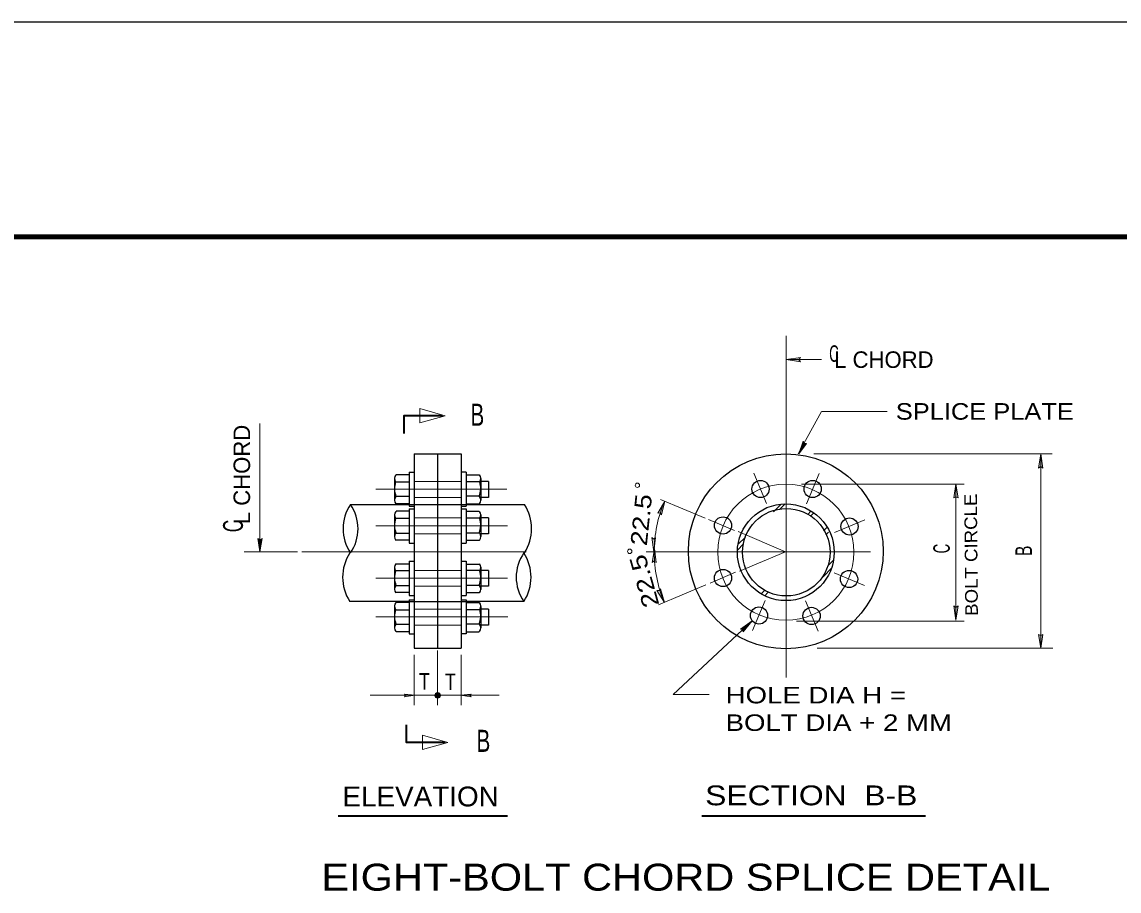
# Model space of a CAD drawing. Extents: x 312601.858 to 312602.699, y 144420.109 to 144420.704.
# Drawn here: x 312602.0898 to 312602.2889, y 144420.5457 to 144420.7035 of the extents above; entities that cross this region are included whole.
import ezdxf
from ezdxf.enums import TextEntityAlignment as Align

# ---------------------------------------------------------------- set-up
doc = ezdxf.new("R2010")
doc.units = 0
doc.header["$LTSCALE"] = 0.0012
for name, pattern in [('DOT_DASHED', [7.7, 5, -1.2, 0.3, -1.2]), ('LONG_DASHED', [7.5, 6, -1.5]), ('MEDIUM_DASHED', [4.5, 3, -1.5])]:
    doc.linetypes.add(name, pattern=pattern)
for name, color, linetype, lineweight in [('1', 7, 'Continuous', 25), ('2', 7, 'Continuous', 13), ('39', 7, 'Continuous', 13), ('9', 7, 'Continuous', 13)]:
    doc.layers.add(name, color=color, linetype=linetype, lineweight=lineweight)

msp = doc.modelspace()

# ---------------------------------------------------------------- hatches: boundary and pattern name
at = {"layer": '1'}
msp.add_hatch(color=256, dxfattribs=at).paths.add_polyline_path([(312602.16575, 144420.58125, 1), (312602.16473, 144420.58125, 1)])
at = {"layer": '39'}
for points in [[(312602.2308, 144420.6422), (312602.2311, 144420.6418), (312602.2285, 144420.6422), (312602.2311, 144420.6426)], [(312602.2318, 144420.627), (312602.2322, 144420.627), (312602.2308, 144420.6251), (312602.2316, 144420.6274)], [(312602.2747, 144420.6228), (312602.2743, 144420.6225), (312602.2747, 144420.6251), (312602.2751, 144420.6225)], [(312602.2747, 144420.6228), (312602.2743, 144420.6225), (312602.2747, 144420.6251), (312602.2751, 144420.6225)], [(312602.2593, 144420.6173), (312602.2589, 144420.6171), (312602.2593, 144420.6196), (312602.2597, 144420.6171)], [(312602.2593, 144420.6173), (312602.2589, 144420.6171), (312602.2593, 144420.6196), (312602.2597, 144420.6171)], [(312602.2056, 144420.6144), (312602.2052, 144420.6143), (312602.2065, 144420.6165), (312602.2059, 144420.614)], [(312602.2045, 144420.6096), (312602.2048, 144420.6099), (312602.2045, 144420.6073), (312602.2041, 144420.6099)], [(312602.133, 144420.6095), (312602.1334, 144420.6097), (312602.133, 144420.6073), (312602.1326, 144420.6097)], [(312602.133, 144420.6095), (312602.1334, 144420.6097), (312602.133, 144420.6073), (312602.1326, 144420.6097)], [(312602.2045, 144420.6056), (312602.2042, 144420.6054), (312602.2046, 144420.6079), (312602.2049, 144420.6054)], [(312602.2055, 144420.6003), (312602.2057, 144420.6006), (312602.2064, 144420.5981), (312602.205, 144420.6003)], [(312602.2593, 144420.5972), (312602.2597, 144420.5975), (312602.2593, 144420.5949), (312602.2589, 144420.5975)], [(312602.2206, 144420.5932), (312602.2202, 144420.5933), (312602.2223, 144420.5948), (312602.2207, 144420.5928)], [(312602.2747, 144420.5921), (312602.2751, 144420.5923), (312602.2747, 144420.5898), (312602.2743, 144420.5923)]]:
    msp.add_hatch(color=256, dxfattribs=at).paths.add_polyline_path(points)

# ---------------------------------------------------------------- linework, layer by layer
at = {"layer": '1', "lineweight": 13}
for p, q in [((312602.2285, 144420.6372), (312602.2285, 144420.6465)), ((312602.2285, 144420.6422), (312602.2349, 144420.6422)), ((312602.2349, 144420.6328), (312602.2307, 144420.6251)), ((312602.235, 144420.6328), (312602.2468, 144420.6328)), ((312602.133, 144420.6073), (312602.133, 144420.6306)), ((312602.2335, 144420.6251), (312602.2768, 144420.6251)), ((312602.2747, 144420.5898), (312602.2747, 144420.6251)), ((312602.1745, 144420.6199), (312602.1745, 144420.6201)), ((312602.2313, 144420.6196), (312602.2608, 144420.6196)), ((312602.2593, 144420.5949), (312602.2593, 144420.6196)), ((312602.2138, 144420.6134), (312602.2057, 144420.6168)), ((312602.1745, 144420.6133), (312602.1745, 144420.6135)), ((312602.2284, 144420.6073), (312602.2198, 144420.611)), ((312602.1398, 144420.6073), (312602.1301, 144420.6073)), ((312602.2031, 144420.6073), (312602.2087, 144420.6073)), ((312602.2284, 144420.6073), (312602.22, 144420.6038)), ((312602.1745, 144420.6038), (312602.1745, 144420.6039)), ((312602.2139, 144420.6013), (312602.2053, 144420.5977)), ((312602.1574, 144420.5974), (312602.1574, 144420.5935)), ((312602.1745, 144420.5967), (312602.1745, 144420.5969)), ((312602.208, 144420.5814), (312602.2223, 144420.5948)), ((312602.2304, 144420.5947), (312602.2608, 144420.5947)), ((312602.161, 144420.5886), (312602.161, 144420.5795)), ((312602.1652, 144420.5894), (312602.1652, 144420.5795)), ((312602.1695, 144420.5886), (312602.1695, 144420.5795)), ((312602.2341, 144420.5898), (312602.2769, 144420.5898)), ((312602.153, 144420.5813), (312602.1764, 144420.5813)), ((312602.208, 144420.5814), (312602.2145, 144420.5814))]:
    msp.add_line(p, q, dxfattribs=at)
at = {"layer": '1', "linetype": 'DOT_DASHED', "lineweight": 13}
for p, q in [((312602.2285, 144420.5845), (312602.2285, 144420.6465)), ((312602.2249, 144420.6161), (312602.2226, 144420.6216)), ((312602.2322, 144420.616), (312602.2345, 144420.6215)), ((312602.1778, 144420.6187), (312602.154, 144420.6187)), ((312602.1779, 144420.612), (312602.154, 144420.612)), ((312602.2191, 144420.6112), (312602.2144, 144420.6132)), ((312602.2373, 144420.6108), (312602.2428, 144420.6131)), ((312602.1813, 144420.6073), (312602.1406, 144420.6073)), ((312602.204, 144420.6073), (312602.2438, 144420.6073)), ((312602.1779, 144420.6025), (312602.154, 144420.6025)), ((312602.2193, 144420.6036), (312602.2147, 144420.6016)), ((312602.2372, 144420.6035), (312602.2427, 144420.6012)), ((312602.2247, 144420.5985), (312602.2224, 144420.593)), ((312602.232, 144420.5984), (312602.2343, 144420.5929)), ((312602.178, 144420.5955), (312602.154, 144420.5955))]:
    msp.add_line(p, q, dxfattribs=at)
at = {"layer": '1'}
for p, q in [((312602.161, 144420.6251), (312602.161, 144420.5898)), ((312602.161, 144420.6251), (312602.1695, 144420.6251)), ((312602.1652, 144420.6251), (312602.1652, 144420.5898)), ((312602.1695, 144420.6251), (312602.1695, 144420.5898)), ((312602.1601, 144420.6218), (312602.161, 144420.6218)), ((312602.1601, 144420.6218), (312602.1601, 144420.6156)), ((312602.1704, 144420.6218), (312602.1695, 144420.6218)), ((312602.1704, 144420.6218), (312602.1704, 144420.6156)), ((312602.1574, 144420.6206), (312602.1574, 144420.6167)), ((312602.1576, 144420.62), (312602.1601, 144420.62)), ((312602.1601, 144420.6213), (312602.1577, 144420.6213)), ((312602.1704, 144420.6213), (312602.1728, 144420.6213)), ((312602.1729, 144420.62), (312602.1704, 144420.62)), ((312602.1731, 144420.6206), (312602.1731, 144420.6167)), ((312602.1745, 144420.6201), (312602.1731, 144420.6201)), ((312602.1745, 144420.6201), (312602.1745, 144420.6172)), ((312602.1494, 144420.6159), (312602.1601, 144420.6159)), ((312602.1577, 144420.6174), (312602.1601, 144420.6174)), ((312602.1601, 144420.616), (312602.1577, 144420.616)), ((312602.1728, 144420.6174), (312602.1704, 144420.6174)), ((312602.1704, 144420.616), (312602.1728, 144420.616)), ((312602.1704, 144420.6159), (312602.181, 144420.6159)), ((312602.1745, 144420.6172), (312602.1731, 144420.6172)), ((312602.1574, 144420.614), (312602.1574, 144420.6101)), ((312602.1601, 144420.6147), (312602.1577, 144420.6147)), ((312602.1601, 144420.6156), (312602.161, 144420.6156)), ((312602.1601, 144420.6151), (312602.1601, 144420.6089)), ((312602.1601, 144420.6151), (312602.161, 144420.6151)), ((312602.1695, 144420.6156), (312602.1704, 144420.6156)), ((312602.1695, 144420.6151), (312602.1704, 144420.6151)), ((312602.1704, 144420.6151), (312602.1704, 144420.6089)), ((312602.1704, 144420.6147), (312602.1728, 144420.6147)), ((312602.1731, 144420.614), (312602.1731, 144420.6101)), ((312602.1576, 144420.6134), (312602.1601, 144420.6134)), ((312602.1729, 144420.6134), (312602.1704, 144420.6134)), ((312602.1745, 144420.6135), (312602.1731, 144420.6135)), ((312602.1745, 144420.6135), (312602.1745, 144420.6106)), ((312602.1577, 144420.6107), (312602.1601, 144420.6107)), ((312602.1728, 144420.6107), (312602.1704, 144420.6107)), ((312602.1745, 144420.6106), (312602.1731, 144420.6106)), ((312602.1601, 144420.6094), (312602.1577, 144420.6094)), ((312602.1601, 144420.6089), (312602.161, 144420.6089)), ((312602.1695, 144420.6089), (312602.1704, 144420.6089)), ((312602.1704, 144420.6094), (312602.1728, 144420.6094)), ((312602.1574, 144420.6045), (312602.1574, 144420.6005)), ((312602.16, 144420.6051), (312602.1576, 144420.6051)), ((312602.1576, 144420.6039), (312602.16, 144420.6039)), ((312602.1576, 144420.6039), (312602.1601, 144420.6039)), ((312602.1601, 144420.6051), (312602.1577, 144420.6051)), ((312602.1601, 144420.6056), (312602.1601, 144420.5994)), ((312602.1601, 144420.6056), (312602.161, 144420.6056)), ((312602.1695, 144420.6056), (312602.1704, 144420.6056)), ((312602.1704, 144420.6056), (312602.1704, 144420.5994)), ((312602.1704, 144420.6051), (312602.1728, 144420.6051)), ((312602.1729, 144420.6039), (312602.1704, 144420.6039)), ((312602.1731, 144420.6045), (312602.1731, 144420.6005)), ((312602.1745, 144420.6039), (312602.1731, 144420.6039)), ((312602.1745, 144420.6039), (312602.1745, 144420.6011)), ((312602.1577, 144420.6012), (312602.16, 144420.6012)), ((312602.1577, 144420.6012), (312602.1601, 144420.6012)), ((312602.16, 144420.5999), (312602.1577, 144420.5999)), ((312602.1601, 144420.5999), (312602.1577, 144420.5999)), ((312602.1728, 144420.6012), (312602.1704, 144420.6012)), ((312602.1704, 144420.5999), (312602.1728, 144420.5999)), ((312602.1745, 144420.6011), (312602.1731, 144420.6011)), ((312602.1601, 144420.5983), (312602.1493, 144420.5983)), ((312602.1601, 144420.5981), (312602.1577, 144420.5981)), ((312602.1601, 144420.5981), (312602.1577, 144420.5981)), ((312602.1601, 144420.5994), (312602.161, 144420.5994)), ((312602.1601, 144420.5986), (312602.1601, 144420.5924)), ((312602.1601, 144420.5986), (312602.161, 144420.5986)), ((312602.1695, 144420.5994), (312602.1704, 144420.5994)), ((312602.1695, 144420.5986), (312602.1704, 144420.5986)), ((312602.1704, 144420.5986), (312602.1704, 144420.5924)), ((312602.1809, 144420.5983), (312602.1704, 144420.5983)), ((312602.1704, 144420.5981), (312602.1728, 144420.5981)), ((312602.1574, 144420.5974), (312602.1574, 144420.5935)), ((312602.1576, 144420.5968), (312602.1601, 144420.5968)), ((312602.1729, 144420.5968), (312602.1704, 144420.5968)), ((312602.1731, 144420.5974), (312602.1731, 144420.5935)), ((312602.1745, 144420.5969), (312602.1731, 144420.5969)), ((312602.1745, 144420.5969), (312602.1745, 144420.594)), ((312602.1577, 144420.5942), (312602.1601, 144420.5942)), ((312602.1577, 144420.5942), (312602.1601, 144420.5942)), ((312602.1728, 144420.5942), (312602.1704, 144420.5942)), ((312602.1745, 144420.594), (312602.1731, 144420.594)), ((312602.1601, 144420.5928), (312602.1577, 144420.5928)), ((312602.1601, 144420.5928), (312602.1577, 144420.5928)), ((312602.1601, 144420.5924), (312602.161, 144420.5924)), ((312602.1704, 144420.5924), (312602.1695, 144420.5924)), ((312602.1704, 144420.5928), (312602.1728, 144420.5928)), ((312602.161, 144420.5898), (312602.1695, 144420.5898))]:
    msp.add_line(p, q, dxfattribs=at)
at = {"layer": '1', "linetype": 'MEDIUM_DASHED', "lineweight": 13}
for p, q in [((312602.1695, 144420.6201), (312602.161, 144420.6201)), ((312602.1695, 144420.6172), (312602.1611, 144420.6172)), ((312602.1695, 144420.6135), (312602.161, 144420.6135)), ((312602.1695, 144420.6106), (312602.1611, 144420.6106)), ((312602.1695, 144420.6039), (312602.161, 144420.6039)), ((312602.1695, 144420.6011), (312602.1611, 144420.6011)), ((312602.1695, 144420.5969), (312602.161, 144420.5969)), ((312602.1695, 144420.594), (312602.1611, 144420.594))]:
    msp.add_line(p, q, dxfattribs=at)
at = {"layer": '1', "linetype": 'LONG_DASHED'}
for p, q in [((312602.1548, 144420.6159), (312602.1588, 144420.6159)), ((312602.1602, 144420.6159), (312602.1703, 144420.6159)), ((312602.1601, 144420.5983), (312602.1703, 144420.5983))]:
    msp.add_line(p, q, dxfattribs=at)
at = {"layer": '1', "lineweight": 35}
for points in [[(312602.1661, 144420.632), (312602.1591, 144420.632), (312602.1591, 144420.6288)], [(312602.1666, 144420.5727), (312602.1596, 144420.5727), (312602.1596, 144420.5759)]]:
    msp.add_lwpolyline(points, dxfattribs=at)
at = {"layer": '1'}
for centre, radius in [((312602.228435, 144420.607405), 0.017693), ((312602.223845, 144420.61871), 0.00156), ((312602.233303, 144420.618715), 0.00156), ((312602.228435, 144420.607235), 0.008788), ((312602.22852, 144420.607235), 0.007942), ((312602.21704, 144420.612103), 0.00156), ((312602.239995, 144420.61191), 0.00156), ((312602.217045, 144420.60256), 0.00156), ((312602.239915, 144420.602367), 0.00156), ((312602.223567, 144420.595755), 0.00156), ((312602.23311, 144420.595675), 0.00156)]:
    msp.add_circle(centre, radius, dxfattribs=at)
at = {"layer": '1', "linetype": 'DOT_DASHED', "lineweight": 13}
msp.add_circle((312602.228435, 144420.607235), 0.012354, dxfattribs=at)
at = {"layer": '1', "lineweight": 13}
msp.add_circle((312602.16524, 144420.58125), 0.00051, dxfattribs=at)
at = {"layer": '1'}
for centre, radius, start, end in [((312602.161585, 144420.61882), 0.004169, 163.41266, 200.28256), ((312602.158525, 144420.620605), 0.001105, 142.02013, 212.47565), ((312602.168895, 144420.61882), 0.004169, 339.71744, 16.58734), ((312602.171955, 144420.620605), 0.001105, 327.52435, 37.97987), ((312602.158525, 144420.616695), 0.001105, 142.02013, 217.97987), ((312602.171955, 144420.616695), 0.001105, 322.02013, 37.97987), ((312602.158525, 144420.613975), 0.001105, 142.02013, 212.47565), ((312602.171955, 144420.613975), 0.001105, 327.52435, 37.97987), ((312602.161585, 144420.61219), 0.004169, 163.41266, 200.28256), ((312602.168895, 144420.61219), 0.004169, 339.71744, 16.58734), ((312602.158525, 144420.610065), 0.001105, 142.02013, 217.97987), ((312602.171955, 144420.610065), 0.001105, 322.02013, 37.97987), ((312602.161585, 144420.60267), 0.004169, 163.41266, 200.28256), ((312602.158525, 144420.604455), 0.001105, 142.02013, 212.47565), ((312602.168895, 144420.60267), 0.004169, 339.71744, 16.58734), ((312602.171955, 144420.604455), 0.001105, 327.52435, 37.97987), ((312602.158525, 144420.600545), 0.001105, 142.02013, 217.97987), ((312602.171955, 144420.600545), 0.001105, 322.02013, 37.97987), ((312602.158525, 144420.597425), 0.001105, 142.02013, 212.47565), ((312602.171955, 144420.597425), 0.001105, 327.52435, 37.97987), ((312602.161585, 144420.59564), 0.004169, 163.41266, 200.28256), ((312602.168895, 144420.59564), 0.004169, 339.71744, 16.58734), ((312602.158525, 144420.593515), 0.001105, 142.02013, 217.97987), ((312602.171955, 144420.593515), 0.001105, 322.02013, 37.97987)]:
    msp.add_arc(centre, radius, start, end, dxfattribs=at)
at = {"layer": '1', "lineweight": 13}
for centre, radius, start, end in [((312602.228435, 144420.607235), 0.023885, 157.17624, 179.78525), ((312602.228435, 144420.607235), 0.023885, 179.79611, 179.80295), ((312602.228435, 144420.607235), 0.023885, 179.7961, 202.45151), ((312602.158525, 144420.597425), 0.001105, 142.02013, 212.47565), ((312602.161585, 144420.59564), 0.004169, 163.41266, 200.28256), ((312602.158525, 144420.593515), 0.001105, 142.02013, 217.97987)]:
    msp.add_arc(centre, radius, start, end, dxfattribs=at)
at = {"layer": '2'}
for p, q in [((312602.2262, 144420.6146), (312602.2275, 144420.6159)), ((312602.2273, 144420.615), (312602.2283, 144420.616)), ((312602.2324, 144420.6141), (312602.233, 144420.6147)), ((312602.2329, 144420.6138), (312602.2335, 144420.6144)), ((312602.2198, 144420.6087), (312602.2211, 144420.61)), ((312602.2353, 144420.6111), (312602.2359, 144420.6117)), ((312602.2357, 144420.6104), (312602.2362, 144420.6109)), ((312602.2197, 144420.6077), (312602.2207, 144420.6087)), ((312602.2361, 144420.6048), (312602.2371, 144420.6058)), ((312602.2352, 144420.6028), (312602.2368, 144420.6044)), ((312602.2239, 144420.5996), (312602.2245, 144420.6002)), ((312602.2246, 144420.5993), (312602.2252, 144420.5999))]:
    msp.add_line(p, q, dxfattribs=at)
at = {"layer": '2', "lineweight": 35}
for p, q in [((312602.1472, 144420.5594), (312602.1779, 144420.5594)), ((312602.2132, 144420.5594), (312602.2538, 144420.5594))]:
    msp.add_line(p, q, dxfattribs=at)
at = {"layer": '2'}
for points in [[(312602.1592, 144420.5815), (312602.1611, 144420.5813), (312602.1592, 144420.581), (312602.1594, 144420.5813)], [(312602.1713, 144420.5815), (312602.1694, 144420.5813), (312602.1713, 144420.581), (312602.1711, 144420.5813)]]:
    msp.add_lwpolyline(points, close=True, dxfattribs=at)
for centre in [(312602.2015, 144420.6194), (312602.2001, 144420.6074)]:
    msp.add_circle(centre, 0.0004, dxfattribs=at)
at = {"layer": '2', "lineweight": 25}
for centre, radius, start, end in [((312602.156192, 144420.6115), 0.008093, 147.06517, 212.93482), ((312602.143186, 144420.6115), 0.007614, 324.69975, 35.30025), ((312602.174208, 144420.6115), 0.008093, 327.06517, 32.93482), ((312602.156092, 144420.6027), 0.008093, 147.06517, 212.93482), ((312602.187114, 144420.6027), 0.007614, 144.69975, 215.30025), ((312602.174108, 144420.6027), 0.008093, 327.06517, 32.93482)]:
    msp.add_arc(centre, radius, start, end, dxfattribs=at)
at = {"layer": '39', "lineweight": 25}
msp.add_line((312601.8578, 144420.7035), (312602.6988, 144420.7035), dxfattribs=at)
at = {"layer": '39', "lineweight": 158}
msp.add_line((312601.9088, 144420.6645), (312602.6838, 144420.6645), dxfattribs=at)
at = {"layer": '39'}
for points in [[(312602.2308, 144420.6422), (312602.2311, 144420.6418), (312602.2285, 144420.6422), (312602.2311, 144420.6426)], [(312602.2318, 144420.627), (312602.2322, 144420.627), (312602.2308, 144420.6251), (312602.2316, 144420.6274)], [(312602.2747, 144420.6228), (312602.2743, 144420.6225), (312602.2747, 144420.6251), (312602.2751, 144420.6225)], [(312602.2747, 144420.6228), (312602.2743, 144420.6225), (312602.2747, 144420.6251), (312602.2751, 144420.6225)], [(312602.2593, 144420.6173), (312602.2589, 144420.6171), (312602.2593, 144420.6196), (312602.2597, 144420.6171)], [(312602.2593, 144420.6173), (312602.2589, 144420.6171), (312602.2593, 144420.6196), (312602.2597, 144420.6171)], [(312602.2056, 144420.6144), (312602.2052, 144420.6143), (312602.2065, 144420.6165), (312602.2059, 144420.614)], [(312602.2045, 144420.6096), (312602.2048, 144420.6099), (312602.2045, 144420.6073), (312602.2041, 144420.6099)], [(312602.133, 144420.6095), (312602.1334, 144420.6097), (312602.133, 144420.6073), (312602.1326, 144420.6097)], [(312602.133, 144420.6095), (312602.1334, 144420.6097), (312602.133, 144420.6073), (312602.1326, 144420.6097)], [(312602.2045, 144420.6056), (312602.2042, 144420.6054), (312602.2046, 144420.6079), (312602.2049, 144420.6054)], [(312602.2055, 144420.6003), (312602.2057, 144420.6006), (312602.2064, 144420.5981), (312602.205, 144420.6003)], [(312602.2593, 144420.5972), (312602.2597, 144420.5975), (312602.2593, 144420.5949), (312602.2589, 144420.5975)], [(312602.2206, 144420.5932), (312602.2202, 144420.5933), (312602.2223, 144420.5948), (312602.2207, 144420.5928)], [(312602.2747, 144420.5921), (312602.2751, 144420.5923), (312602.2747, 144420.5898), (312602.2743, 144420.5923)]]:
    msp.add_lwpolyline(points, close=True, dxfattribs=at)
at = {"layer": '9'}
for points in [[(312602.162, 144420.6307), (312602.1666, 144420.632), (312602.162, 144420.6333)], [(312602.1625, 144420.5714), (312602.1671, 144420.5727), (312602.1625, 144420.574)]]:
    msp.add_lwpolyline(points, close=True, dxfattribs=at)

# ---------------------------------------------------------------- texts
at = {"layer": '2'}
for s, width, p in [('C', 0.6, (312602.2363, 144420.6418)), ('HOLE DIA H = ', 1.25, (312602.2175, 144420.5798)), ('BOLT DIA + 2 MM', 1.25, (312602.2175, 144420.5748))]:
    msp.add_text(s, height=0.003, dxfattribs=dict(at, width=width)).set_placement(p)
msp.add_text('L CHORD', height=0.003, dxfattribs=at).set_placement((312602.2372, 144420.6407))
for s, height, width, p in [('B', 0.004, 0.7, (312602.17245, 144420.6302)), ('SPLICE PLATE', 0.003, 1.15, (312602.26455, 144420.6313)), ('T', 0.003, 0.8, (312602.16285, 144420.5823)), ('T', 0.003, 0.8, (312602.16755, 144420.5822)), ('B', 0.004, 0.7, (312602.17355, 144420.571)), ('ELEVATION', 0.0036, 1.05, (312602.16215, 144420.5611)), ('SECTION  B-B', 0.0036, 1.2, (312602.23305, 144420.5613)), ('EIGHT-BOLT CHORD SPLICE DETAIL', 0.0049, 1.15, (312602.2103, 144420.5458))]:
    msp.add_text(s, height=height, dxfattribs=dict(at, width=width)).set_placement(p, align=Align.CENTER)
msp.add_text('L CHORD', height=0.003, rotation=90, dxfattribs=at).set_placement((312602.1312, 144420.62135), align=Align.CENTER)
for s, height, rotation, width, p in [('BOLT CIRCLE', 0.0023, 90.492, 1.1, (312602.2633, 144420.5957)), ('22.5', 0.003, 84.053, 1.2, (312602.2032, 144420.6083)), ('22.5', 0.003, 105.716, 1.25, (312602.2055, 144420.5977))]:
    msp.add_text(s, height=height, rotation=rotation, dxfattribs=dict(at, width=width)).set_placement(p)
for s, height, width, p in [('C', 0.0036, 0.65, (312602.1299, 144420.612)), ('C', 0.003, 0.6, (312602.2582, 144420.6079)), ('B', 0.003, 0.7, (312602.2731, 144420.6075))]:
    msp.add_text(s, height=height, rotation=90, dxfattribs=dict(at, width=width)).set_placement(p, align=Align.CENTER)

doc.saveas('drawing.dxf')
